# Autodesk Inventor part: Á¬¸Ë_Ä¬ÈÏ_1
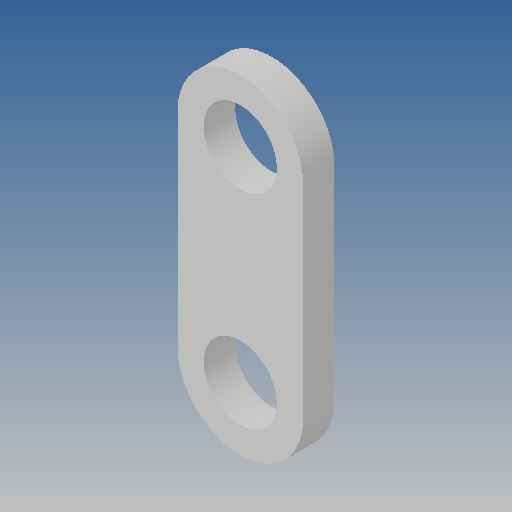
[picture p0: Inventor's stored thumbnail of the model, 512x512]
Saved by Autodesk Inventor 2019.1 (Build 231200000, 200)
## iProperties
Created: 2012-10
Part Number: Á¬¸Ë_Ä¬ÈÏ_1
Material: Ogólny
Document SubType Name: Modeling
Designer: CADENGINEERING4
Density: 1 g/cm^3
Appearance: Domyślna
Author: CADENGINEERING4
Revision Number: ÈÎºÎ
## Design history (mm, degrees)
feature "NONE"
node "Bryła1"
